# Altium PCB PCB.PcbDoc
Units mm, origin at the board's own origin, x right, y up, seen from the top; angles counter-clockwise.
Board outline 82.53 x 49.5 mm, 2 copper layers (Top Layer, Bottom Layer); 55 components, 40 nets, 211 pads, 119 vias.
Unrouted connection lines stored in the file: 2.
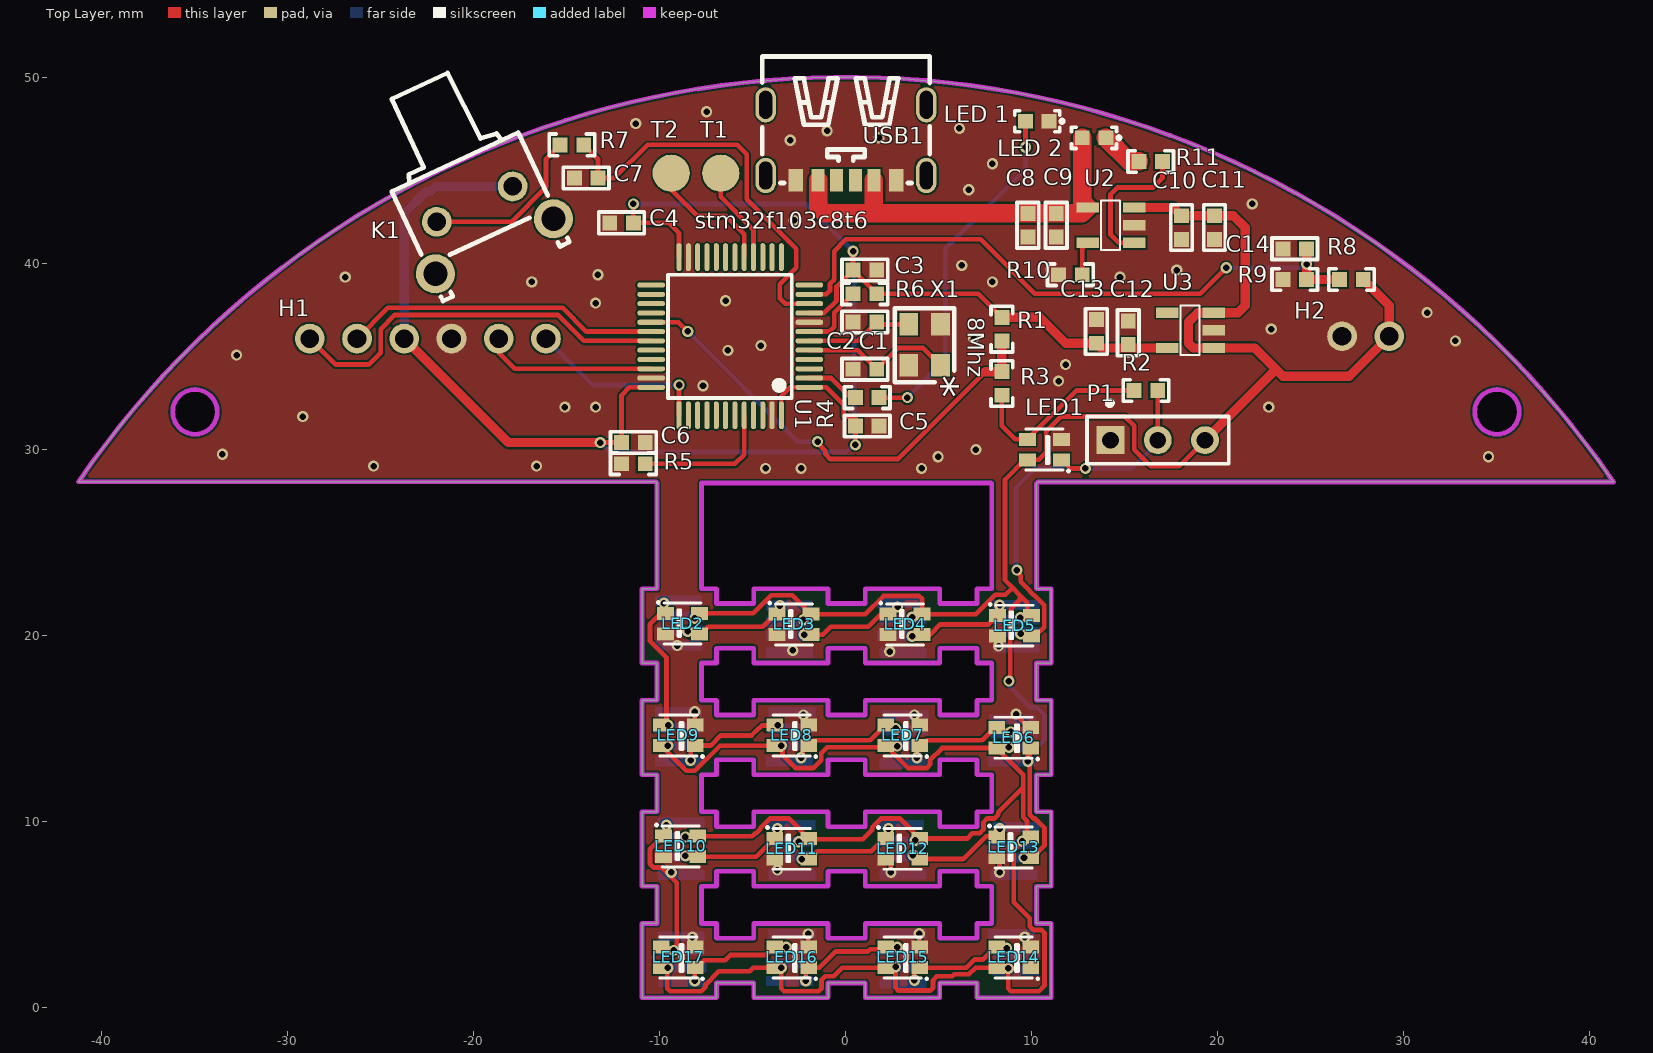
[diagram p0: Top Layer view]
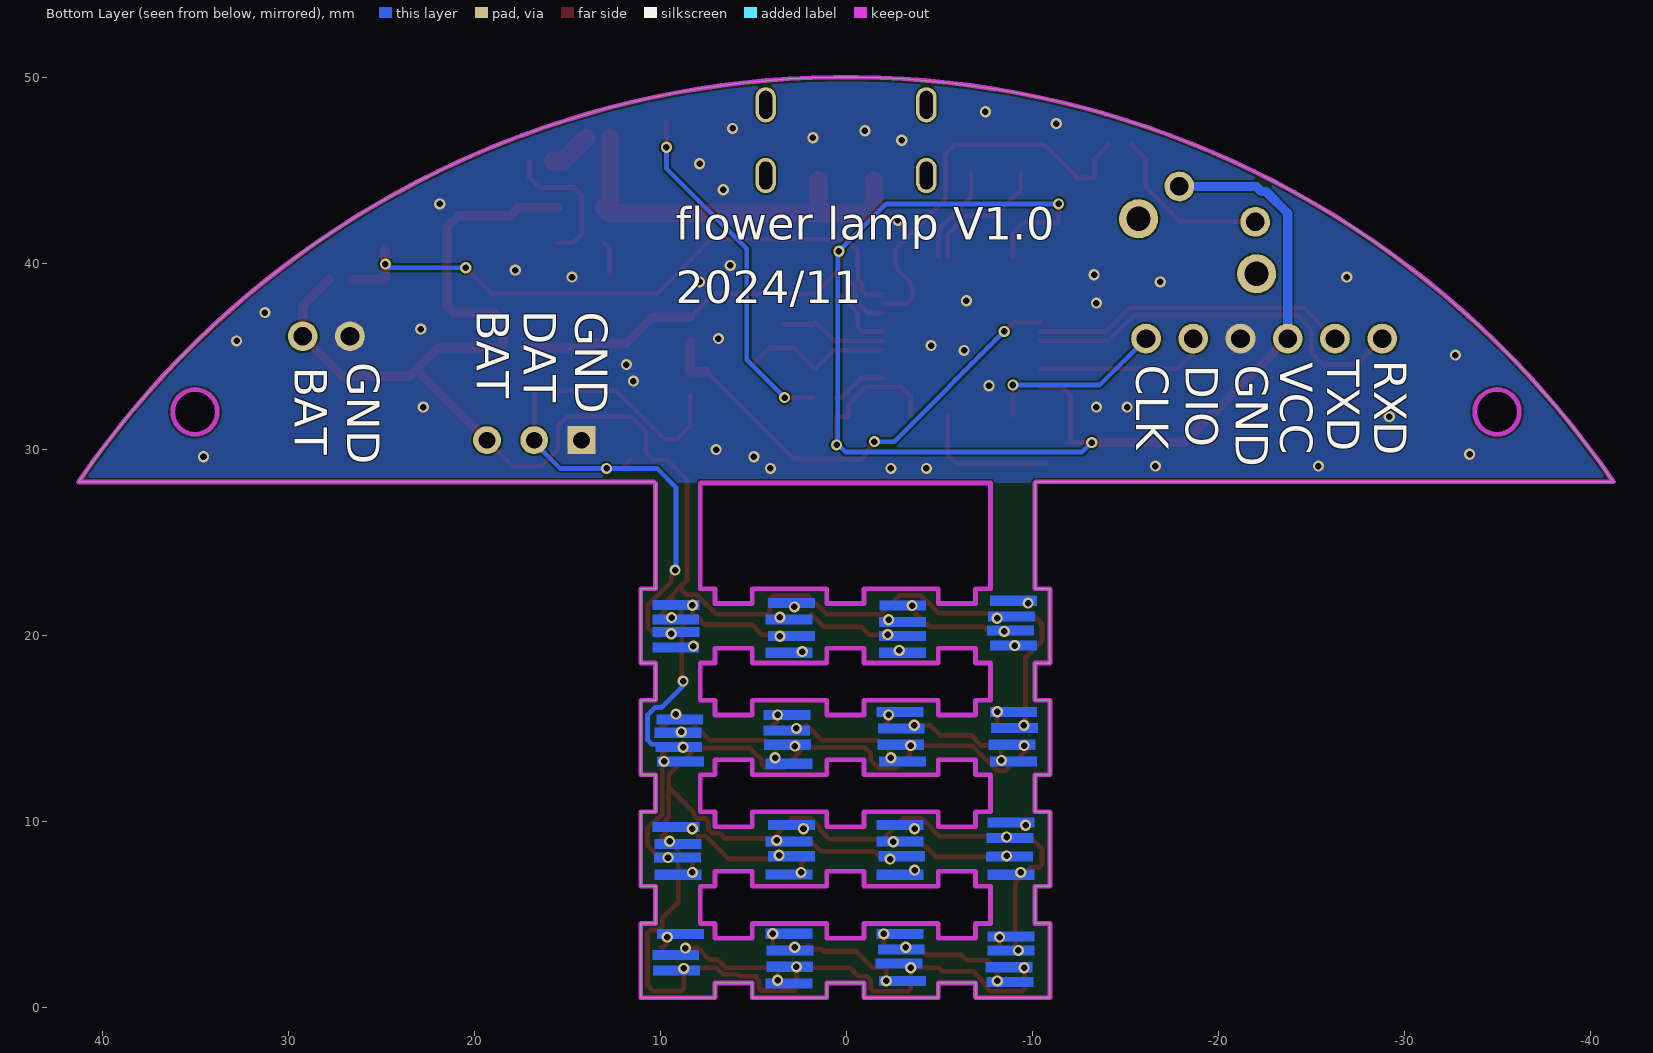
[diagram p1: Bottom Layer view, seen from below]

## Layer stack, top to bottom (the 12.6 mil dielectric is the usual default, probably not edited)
Top Solder: solder mask 0.0102, Solder Resist, Dk 3.5
Top Layer: signal copper 0.0356
Dielectric 1: dielectric 0.32, FR-4, Dk 4.8
Bottom Layer: signal copper 0.0356
Bottom Solder: solder mask 0.0102, Solder Resist, Dk 3.5

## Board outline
-10.962,0.497 -10.962,4.497 -10.162,4.497 -10.162,6.497 -10.962,6.497 -10.962,10.497 -10.162,10.497 -10.162,12.497 -10.962,12.497 -10.962,16.497 -10.162,16.497 -10.162,18.497 -10.962,18.497 -10.962,22.497 -10.162,22.497 -10.162,28.192 -10.206,28.236 -41.264,28.236 cw(c0,0) 41.266,28.233 10.326,28.233 10.238,28.145 10.238,22.497 11.038,22.497 11.038,18.497 10.238,18.497 10.238,16.497 11.038,16.497 11.038,12.497 10.238,12.497 10.238,10.497 11.038,10.497 11.038,6.497 10.238,6.497 10.238,4.497 11.038,4.497 11.038,0.497 7.038,0.497 7.038,1.297 5.038,1.297 5.038,0.497 1.038,0.497 1.038,1.297 -0.962,1.297 -0.962,0.497 -4.962,0.497 -4.962,1.297 -6.962,1.297 -6.962,0.497
cut-out: 33.8,32 ccw(c35,32) 35,30.8 ccw(c35,32) 36.2,32 ccw(c35,32) 35,33.2 ccw(c35,32)
cut-out: -35,30.8 cw(c-35,32) -36.2,32 cw(c-35,32) -35,33.2 cw(c-35,32) -33.8,32 cw(c-35,32)
cut-out: -6.962,21.697 -4.962,21.697 -4.962,22.497 -0.962,22.497 -0.962,21.697 1.038,21.697 1.038,22.497 5.038,22.497 5.038,21.697 7.038,21.697 7.038,22.497 7.838,22.497 7.838,28.158 7.817,28.179 -7.762,28.179 -7.762,22.497 -6.962,22.497
cut-out: -7.762,4.497 -6.962,4.497 -6.962,3.697 -4.962,3.697 -4.962,4.497 -0.962,4.497 -0.962,3.697 1.038,3.697 1.038,4.497 5.038,4.497 5.038,3.697 7.038,3.697 7.038,4.497 7.838,4.497 7.838,6.497 7.038,6.497 7.038,7.297 5.038,7.297 5.038,6.497 1.038,6.497 1.038,7.297 -0.962,7.297 -0.962,6.497 -4.962,6.497 -4.962,7.297 -6.962,7.297 -6.962,6.497 -7.762,6.497
cut-out: -4.962,9.697 -4.962,10.497 -0.962,10.497 -0.962,9.697 1.038,9.697 1.038,10.497 5.038,10.497 5.038,9.697 7.038,9.697 7.038,10.497 7.838,10.497 7.838,12.497 7.038,12.497 7.038,13.297 5.038,13.297 5.038,12.497 1.038,12.497 1.038,13.297 -0.962,13.297 -0.962,12.497 -4.962,12.497 -4.962,13.297 -6.962,13.297 -6.962,12.497 -7.762,12.497 -7.762,10.497 -6.962,10.497 -6.962,9.697
cut-out: -7.762,16.497 -6.962,16.497 -6.962,15.697 -4.962,15.697 -4.962,16.497 -0.962,16.497 -0.962,15.697 1.038,15.697 1.038,16.497 5.038,16.497 5.038,15.697 7.038,15.697 7.038,16.497 7.838,16.497 7.838,18.497 7.038,18.497 7.038,19.297 5.038,19.297 5.038,18.497 1.038,18.497 1.038,19.297 -0.962,19.297 -0.962,18.497 -4.962,18.497 -4.962,19.297 -6.962,19.297 -6.962,18.497 -7.762,18.497

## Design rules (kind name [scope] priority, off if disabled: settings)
Clearance [All] p1: gap=0.1 ignorepadtopadclearanceinfootprint=FALSE except(0: Arc-Hole Track-Hole SMDPad-Hole THPad-Hole Via-Hole Fill-Hole Poly-Hole Region-Hole Text-Hole; 0.102: Arc-Arc Arc-Track Arc-SMDPad Arc-THPad Track-Track Track-SMDPad Track-THPad SMDPad-SMDPad SMDPad-THPad THPad-THPad; 0.127: Arc-Via Track-Via SMDPad-Via SMDPad-Text THPad-Via Via-Via; 0.254: Arc-Text Track-Text THPad-Text Via-Text Fill-Text Poly-Text Region-Text Text-Text)
DiffPairsRouting [All] p1: maxlimit=0.254 minlimit=0.15 mostfreqgap=0.254 toplayer_minwidth=0.2 toplayer_maxwidth=0.381 toplayer_prefwidth=0.25 bottomlayer_minwidth=0.2 bottomlayer_maxwidth=0.381 bottomlayer_prefwidth=0.25 maxuncoupledlength=12.7
HoleSize [All] p1: absolutevalues=TRUE maxlimit=30 minlimit=0.025 maxpercent=80.000 minpercent=20.000
HoleToHoleClearance [All] p1: gap=0.152 allowstackedmicrovias=TRUE
MinimumSolderMaskSliver [All] p1: minsoldermaskwidth=0
PlaneClearance [All] p1: clearance=0.254
PlaneConnect [All] p1: planeconnectstyle=Direct reliefexpansion=0.508 reliefentries=4 reliefconductorwidth=0.254 reliefairgap=0.254
PolygonConnect [All] p1: connectstyle=Direct reliefconductorwidth=0.254 reliefentries=4 polygonreliefangle="90 Angle" airgapwidth=0.254
RoutingVias [All] p1: holewidth=0.711 width=1.27 viastyle="Through Hole" minholewidth=0.3 minwidth=0.5 maxholewidth=30 maxwidth=30
SilkToSilkClearance [All] p1: silktosilkclearance=0
SilkToSolderMaskClearance [IsPad] p1: minsilkscreentomaskgap=0 clearancetoexposedcopper=TRUE
SolderMaskExpansion [All] p1: expansion=0.102 istentingtop=FALSE
Width [All] p1: maxlimit=3 minlimit=0.1 preferedwidth=0.254
22 further rules are at their usual default settings.

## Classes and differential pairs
component class Sheet1: C1 C2 C3 C4 C5 C6 C7 C8 C9 C10 C11 C12 C13 C14 H1 H2 K1 LED1 LED2 LED3 LED4 LED5 LED6 LED7 LED8 LED9 LED10 LED11 LED12 LED13 LED14 LED15 LED16 LED17 "LED 1" "LED 2" P1 R1 R3 R5 R7 R9 R11 T1 T2 U1 U2 U3 USB1 X1

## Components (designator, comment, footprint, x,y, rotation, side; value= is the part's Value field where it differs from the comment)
C1 "12pF" CC1608-0603 1.016,34.29 r0 top
C2 "12pF" CC1608-0603 1.016,36.83 r0 top
C3 "100NF" CC1608-0603 1.016,39.624 r180 top
C4 "100NF" CC1608-0603 -12.065,42.164 r0 top
C5 "100NF" CC1608-0603 1.143,31.242 r180 top
C6 "100NF" CC1608-0603 -11.43,30.353 r180 top
C7 "12pF" CC1608-0603 -13.97,44.577 r0 top
C8 "1UF" CC1608-0603 9.779,42.037 r90 top
C9 "100NF" CC1608-0603 11.303,42.037 r90 top
C10 "1UF" CC1608-0603 18.034,41.91 r90 top
C11 "100NF" CC1608-0603 19.812,41.91 r90 top
C12 "1UF" CC1608-0603 15.179,36.25 r270 top
C13 "100NF" CC1608-0603 13.462,36.322 r270 top
C14 "100PF" CC1608-0603 24.13,40.767 r0 top
H1 "Header_6P_Curved" Header_2_54_6PW -28.829,35.941 r0 top
H2 "Header_2P_Curved" Header_2_54_2PW 26.67,36.068 r0 top
K1 "SW-TH_4P_H" SW-TH_KH-6X6X7H-ZJ -19.431,42.037 r25 top locked
LED1 "WS2812B-2020" WS2812B-2020 10.668,29.972 r180 top
LED2 "WS2812B-2020" WS2812B-2020 -8.789,20.616 r0 top
LED3 "WS2812B-2020" WS2812B-2020 -2.794,20.574 r0 top
LED4 "WS2812B-2020" WS2812B-2020 3.175,20.574 r0 top
LED5 "WS2812B-2020" WS2812B-2020 9.061,20.507 r0 top
LED6 "WS2812B-2020" WS2812B-2020 9.017,14.478 r180 top
LED7 "WS2812B-2020" WS2812B-2020 3.048,14.605 r180 top
LED8 "WS2812B-2020" WS2812B-2020 -2.921,14.605 r180 top
LED9 "WS2812B-2020" WS2812B-2020 -9.017,14.605 r180 top
LED10 "WS2812B-2020" WS2812B-2020 -8.89,8.636 r0 top
LED11 "WS2812B-2020" WS2812B-2020 -2.921,8.509 r0 top
LED12 "WS2812B-2020" WS2812B-2020 3.048,8.509 r0 top
LED13 "WS2812B-2020" WS2812B-2020 9.017,8.585 r0 top
LED14 "WS2812B-2020" WS2812B-2020 9.017,2.667 r180 top
LED15 "WS2812B-2020" WS2812B-2020 3.048,2.667 r180 top
LED16 "WS2812B-2020" WS2812B-2020 -2.921,2.667 r180 top
LED17 "WS2812B-2020" WS2812B-2020 -9.017,2.667 r180 top
"LED 1" "LED 0603" "LED 0603" 10.287,47.625 r0 top
"LED 2" "LED 0603" "LED 0603" 13.335,46.736 r0 top
P1 "Header 3" HDR1X3 14.224,30.48 r0 top
R1 "10K" CR1608-0603 8.382,36.449 r270 top
R2 "0R" CR1608-0603 16.129,33.147 r0 top
R3 "0R" CR1608-0603 8.382,33.528 r270 top
R4 "1K" CR1608-0603 1.143,32.766 r180 top
R5 "10K" CR1608-0603 -11.43,29.21 r0 top
R6 "10K" CR1608-0603 1.016,38.354 r180 top
R7 "1K" CR1608-0603 -14.732,46.355 r180 top
R8 "10K" CR1608-0603 27.178,39.116 r0 top
R9 "10K" CR1608-0603 24.13,39.116 r0 top
R10 "2K" CR1608-0603 12.065,39.37 r0 top
R11 "2K" CR1608-0603 16.383,45.466 r180 top
T1 "test" test -6.731,44.831 r0 top
T2 "test" test -9.398,44.831 r0 top
U1 "STM32F103C8T6" LQFP-48 -6.223,36.068 r90 top locked
U2 "TP4054" SOT23-5 15.494,42.992 r270 top
U3 "RT9013-33GB" SOT23-5 19.772,37.338 r270 top
USB1 "TYPE_C_SMD_6P" TYPE-C-SMD_TYPE-C-6P 0,46.482 r180 top locked
X1 "3225_8M" XTAL-3225 3.38,34.503 r90 top

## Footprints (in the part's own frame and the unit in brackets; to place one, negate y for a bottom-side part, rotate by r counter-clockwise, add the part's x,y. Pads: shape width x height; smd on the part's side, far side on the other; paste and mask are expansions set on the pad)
CC1608-0603 [mm]
  rect 0.8x0.8 smd: 1(-0.635,0) 2(0.635,0)
  silkscreen extent -1.23,-0.58 1.23,0.58, body extent -0.8,-0.4 0.8,0.4, height 0.3
CR1608-0603 [mm]
  rect 0.8x0.8 smd: 1(-0.635,0) 2(0.635,0)
  silkscreen extent -1.23,-0.58 1.23,0.58, body extent -0.8,-0.4 0.8,0.4, height 0.45
HDR1X3 [mm] "Connector; Header; 3 Position"
  rect 1.5x1.5 hole 0.9: 1(0,0)
  round 1.5 hole 0.9: 2(2.54,0) 3(5.08,0)
  silkscreen extent -1.27,-1.27 6.35,2.14, body extent -1.27,-1.27 6.35,1.27, height 8.54
Header_2_54_2PW [mm] "弯的排针"
  round 1.6 hole 1: 1(0,0) 2(2.54,0)
  body extent -2.52,-7.47 5.18,0.38, height 5.8
Header_2_54_6PW [mm] "6P弯针"
  round 1.6 hole 1: 1(0,0) 2(2.54,0) 3(5.08,0) 4(7.62,0) 5(10.16,0) 6(12.7,0)
  body extent -2.56,-7.48 15.3,0.37, height 5.8
"LED 0603" [mm]
  rect 0.8x0.8 smd: 1(-0.635,0) 2(0.635,0)
  silkscreen extent -1.21,-0.57 1.4,0.57, body extent -0.8,-0.4 0.8,0.4, height 0.6
LQFP-48 [mm]
  oval 0.27x1.5 smd: 1(-2.75,-4.25) 2(-2.25,-4.25) 3(-1.75,-4.25) 4(-1.25,-4.25) 5(-0.75,-4.25) 6(-0.25,-4.25) 7(0.25,-4.25) 8(0.75,-4.25) 9(1.25,-4.25) 10(1.75,-4.25) 11(2.25,-4.25) 12(2.75,-4.25) 25(2.75,4.25) 26(2.25,4.25) 27(1.75,4.25) 28(1.25,4.25) 29(0.75,4.25) 30(0.25,4.25) 31(-0.25,4.25) 32(-0.75,4.25) 33(-1.25,4.25) 34(-1.75,4.25) 35(-2.25,4.25) 36(-2.75,4.25)
  oval 1.5x0.27 smd: 13(4.25,-2.75) 14(4.25,-2.25) 15(4.25,-1.75) 16(4.25,-1.25) 17(4.25,-0.75) 18(4.25,-0.25) 19(4.25,0.25) 20(4.25,0.75) 21(4.25,1.25) 22(4.25,1.75) 23(4.25,2.25) 24(4.25,2.75) 37(-4.25,2.75) 38(-4.25,2.25) 39(-4.25,1.75) 40(-4.25,1.25) 41(-4.25,0.75) 42(-4.25,0.25) 43(-4.25,-0.25) 44(-4.25,-0.75) 45(-4.25,-1.25) 46(-4.25,-1.75) 47(-4.25,-2.25) 48(-4.25,-2.75)
  silkscreen extent -3.33,-3.31 3.3,3.34, body extent -4.47,-4.54 4.53,4.46, height 1.56
SOT23-5 [mm] "适用于MIC5205"
  rect 0.55x1.2 smd: 1(1.905,0) 2(0.955,0) 3(0.005,0) 4(0.005,-2.5) 5(1.905,-2.5)
  silkscreen extent -0.38,-1.78 2.29,-0.76, body extent -0.6,-2.82 2.5,0.38, height 1.45
SW-TH_KH-6X6X7H-ZJ [mm]
  round 1.6 hole 1 paste+0 mask+0.05: 1(2.25,1.25) 2(-2.25,1.25)
  round 2.1 hole 1.3 paste+0 mask+0.05: 3(3.5,-1.25) 4(-3.5,-1.25)
  silkscreen extent -3.75,-2.75 3.75,8.25, body extent -3.75,-2.48 3.75,5.67, height 7.5
test [mm]
  round 2 smd: 0(0,0)
TYPE-C-SMD_TYPE-C-6P [mm]
  oval 1.1x1.9 hole 0.7 slot 1.5 at 90 deg paste+0 mask+0.051: 7(-4.32,-2.025) 7(-4.32,1.775) 7(4.32,-2.025) 7(4.32,1.775)
  rect 0.7x1.2 smd paste-100 mask+0.051: A5(-0.5,2.025) A9(1.5,2.025) B5(0.5,2.025) B9(-1.5,2.025)
  rect 0.8x1.2 smd paste-100 mask+0.051: A12(2.7,2.025) B12(-2.7,2.025)
  silkscreen extent -4.5,-4.63 4.5,2.18, body extent -4.44,-4.47 4.49,2.43, height 3.18
WS2812B-2020 [mm]
  rect 0.9x0.7 smd paste+0 mask+0.051: 1(-0.915,0.55) 2(-0.915,-0.55) 3(0.915,-0.55) 4(0.915,0.55)
  silkscreen extent -1.3,-1.1 1,1.15, body extent -1.1,-1 1.1,1, height 0.84
XTAL-3225 [mm]
  rect 1.2x1 smd: 1(0,-1.7) 2(2.2,-1.7) 3(2.2,0) 4(0,0)
  silkscreen extent -0.91,-2.44 3.07,0.76, body extent -0.43,-2.15 2.77,0.35, height 0.61

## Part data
C1 C2 C3 C4 C5 C6 C7 C8 C9 C10 C11 C12 C13 C14: library part "Cap Chip 0603", "0603封装的电容"
H1: "弯的6P排针"
H2: "弯的2P排针"
K1: "卧式轻触开关"
LED1 LED2 LED3 LED4 LED5 LED6 LED7 LED8 LED9 LED10 LED11 LED12 LED13 LED14 LED15 LED16 LED17: JLCPCB Part Class="Extended Part", Manufacturer=worldsemi
P1: "Header, 3-Pin"
R1 R2 R3 R4 R5 R6 R7 R8 R9 R10 R11: library part "Resistor Chip 0603", "0603封装电阻"
T1 T2: "测试点"
U1: JLCPCB Part Class="Basic Part", Manufacturer=ST(意法半导体)
U2: "迷你充电IC SOT-23-5"
U3: "LDO 2.2-5.2V IN 500Ma OUT SOT23-5"
USB1: JLCPCB Part Class="Extended Part", Manufacturer=null
X1: library part "XTAL 3225", "3225封装的晶振"

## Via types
v1: diameter 0.6, hole 0.35, Top Layer to Bottom Layer, tented both sides, 119 vias

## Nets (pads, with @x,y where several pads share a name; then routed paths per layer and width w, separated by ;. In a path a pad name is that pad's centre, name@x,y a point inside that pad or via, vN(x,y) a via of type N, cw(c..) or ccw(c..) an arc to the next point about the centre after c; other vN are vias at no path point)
5V: "LED 2.1" C8.2 C9.2 U2.4 USB1.A9 USB1.B9 | length 22
  Top Layer w1: USB1.A9 -1.5,43.029 -1.143,42.672 1.778,42.672 ; USB1.B9 1.5,42.95 1.778,42.672 ; 12.7,46.736 12.7,43.281 U2.4 12.679,42.672 C9.2 C8.2 1.778,42.672
ADCIN1: C14.2 R8.1 R9.2 U1.11 | length 34.4
  Top Layer w0.254: U1.11 -1.052,38.318 -0.864,38.506 -0.864,38.882 -0.635,39.111 -0.635,40.64 0,41.275 7.239,41.275 10.16,38.354 19.05,38.354 v1(20.447,39.751)
  Top Layer w0.5: C14.2 v1(24.765,39.941) R9.2 R8.1
  Bottom Layer w0.254: v1(20.447,39.751) 24.575,39.751 v1(24.765,39.941)
BAT: C10.2 C11.2 H2.2 LED1.4 LED2.4 LED3.4 LED4.4 LED5.4 LED6.4 LED7.4 LED8.4 LED9.4 LED10.4 LED11.4 LED12.4 LED13.4 LED14.4 LED15.4 LED16.4 LED17.4 P1.3 R8.2 U2.3 U3.1 U3.3 | length 178.7
  Top Layer w0.254: LED17.4 -9.832,2.117 -9.609,1.894 -9.609,1.001 -9.46,0.853 -7.783,0.853 -7.55,1.086 -7.55,1.211 -6.831,1.93 -5.176,1.93 -4.99,2.117 LED16.4 v1(-3.481,2.117) -3.481,1.001 -3.332,0.853 -1.466,0.853 -1.318,1.001 -1.318,1.444 -1.109,1.653 -0.666,1.653 -0.202,2.117 LED15.4 2.154,2.138 2.646,2.138 v1(2.667,2.159) 2.667,1.038 2.816,0.889 4.534,0.889 4.682,1.038 4.682,1.444 4.891,1.653 5.717,1.653 5.825,1.761 6.611,1.761 6.967,2.117 LED14.4 8.202,2.117 8.223,2.096 v1@8.699,2.096 ; LED9.4 -8.577,12.7 -8.128,12.7 -6.773,14.055 LED8.4 v1(-3.481,14.055) -3.415,13.989 -3.415,13.575 -2.693,12.853 -1.752,12.853 -1.327,13.278 -1.327,13.659 -1.016,13.97 2.048,13.97 LED7.4 ; LED10.4 -5.038,9.186 -4.883,9.341 -4.815,9.341 -4.606,9.55 -4.606,9.618 -4.083,10.141 -3.088,10.141 -1.964,9.017 0.905,9.017 1.331,9.443 1.394,9.505 cw(c1.739,9.505) 1.494,9.749 1.886,10.141 2.881,10.141 LED12.4 ; LED2.4 -4.99,21.166 -4.015,22.141 -2.896,22.141 LED3.4 1.043,21.124 2.017,22.098 3.941,22.098 4.09,21.949 LED4.4 6.989,21.124 8.026,22.161 8.572,22.161 8.954,22.543 ; v1(2.743,14.03) 2.731,14.042 2.245,14.042 2.456,13.832 2.456,13.732 3.335,12.853 4.344,12.853 4.513,13.022 4.513,13.275 5.166,13.928 LED6.4 ; v1(3.728,8.964) 3.868,8.964 LED12.4 ; v1(8.721,2.074) 8.721,1.001 8.869,0.853 10.378,0.853 10.668,1.143 10.668,3.993 10.519,4.141 10.091,4.141 9.882,4.35 9.882,4.778 9.017,5.644 9.017,8.414 9.482,8.879 v1(9.482,8.912) ; v1(8.763,13.97) 8.624,13.97 8.603,13.949 8.123,13.949 LED6.4 ; v1(8.763,17.526) 8.825,17.588 8.825,20.402 8.782,20.444 8.782,20.57 8.871,20.658 8.871,21.417 9.353,21.899 9.353,22.143 ; v1(9.379,20.936) 9.439,20.997 9.682,20.997 LED5.4@9.859,21.174 ; LED13.4@9.705,9.135 LED13.4@9.609,9.039 ; LED13.4@9.805,9.135 LED13.4 9.736,9.331 9.736,9.993 9.527,10.202 9.527,11.813 ; LED5.4 LED5.4@9.859,21.174 ; P1.3 17.907,29.083 16.383,29.083 15.494,29.972 15.494,31.242 14.986,31.75 11.557,31.75 10.768,30.961 10.768,29.818 10.372,29.422 LED1.4 9.61,29.422 8.549,28.361 8.549,22.947 8.954,22.543 ; LED12.4 6.519,9.059 6.801,9.341 7.185,9.341 7.394,9.55 7.394,9.934 7.601,10.141 7.985,10.141 8.194,10.35 8.194,10.48 9.527,11.813 ; LED6.4 9.527,12.503 9.527,11.813 ; 8.954,22.543 9.353,22.143 ; 9.353,22.143 9.753,21.743 9.753,21.28 LED5.4@9.859,21.174 ; v1(9.482,8.912) 9.609,8.912 LED13.4@9.609,9.039 ; v1(9.482,8.912) LED13.4@9.609,9.039
  Top Layer w0.5: U2.3 17.592,42.987 C10.2 C11.2 20.828,42.545 21.463,41.91 21.463,37.719 21.077,37.333 U3.3 18.918,37.333 18.415,36.83 18.415,35.687 18.669,35.433 U3.1 21.971,35.433 23.05,34.353 ; P1.3 23.05,34.227 23.05,34.353 ; R8.2 29.21,37.719 H2.2 27.051,33.909 23.495,33.909 23.05,34.353
  Bottom Layer w0.254: -8.898,20.995 -8.206,20.995 v1(-8.119,20.907) ; v1(2.743,14.03) 3.073,14.03 3.149,14.105 ; 3.199,8.959 3.204,8.964 v1(3.728,8.964) ; v1(8.763,17.526) 8.763,17.272 9.933,16.102 10.284,16.102 10.668,15.718 10.668,14.351 10.445,14.128 9.567,14.128 ; v1@9.136,20.907 9.35,20.907 v1(9.379,20.936)
  other v1: -9.577,2.117 -2.54,8.89 -8.636,9.144 -9.577,14.055 -2.286,20.828 3.556,20.955
BOOT0: R5.2 U1.44 | length 7.6
  Top Layer w0.254: R5.2 -5.969,29.21 -5.473,29.706 U1.44
DO: LED1.1 LED5.3 P1.2 R2.2 | length 22.1
  Top Layer w0.254: v1(9.191,23.495) 9.191,23.401 9.398,23.194 9.398,22.872 9.882,22.388 9.882,22.35 10.091,22.141 10.129,22.141 10.655,21.615 10.655,20.434 10.178,19.957 LED5.3 ; LED1.1 12.049,28.956 v1@12.827,28.956 ; P1.2 R2.2
  Bottom Layer w0.254: v1@9.144,23.495 9.144,27.94 10.16,28.956 v1(12.874,28.956) 15.367,28.956 16.764,30.353 P1.2 ; v1@9.259,20.223 9.398,20.085 v1(9.398,20.075)
GND: "LED 1.2" C1.1 C2.1 C3.1 C4.1 C5.1 C6.1 C7.1 C8.1 C9.1 C10.1 C11.1 C12.1 C13.1 C14.1 H1.4 H2.1 LED1.2 LED2.2 LED3.2 LED4.2 LED5.2 LED6.2 LED7.2 LED8.2 LED9.2 LED10.2 LED11.2 LED12.2 LED13.2 LED14.2 LED15.2 LED16.2 LED17.2 P1.1 R5.1 R9.1 R10.1 U1.8 U1.23 U1.35 U1.47 U2.2 U3.2 USB1.A12 USB1.B12 X1.2 X1.4 | length 7.8
  Top Layer w0.254: v1(-8.255,3.767) -8.255,3.37 LED17.2 ; v1(-8.128,15.875) -8.128,15.181 LED9.2 ; v1(-2.286,15.705) -2.286,15.378 -2.063,15.155 LED8.2 ; v1(-2.032,3.937) -2.032,3.243 LED16.2 ; LED12.2 2.19,7.959 2.413,7.736 v1(2.413,7.239) ; v1(3.683,15.705) 3.683,15.378 3.906,15.155 LED7.2 ; v1(3.937,3.943) 3.937,3.243 LED15.2 ; LED13.2 8.255,7.882 v1(8.255,7.239) ; v1(9.144,15.748) 9.144,15.716 9.832,15.028 LED6.2 ; v1(9.609,3.767) 9.609,3.44 9.832,3.217 LED14.2
  other v1: -3.683,7.366 2.35,19.114 -2.862,19.177 8.209,19.407 -9.069,19.431 -4.318,28.956 -2.413,28.956 4.064,28.956 -25.4,29.083 -16.637,29.083 4.953,29.591 34.544,29.591 -33.528,29.718 6.985,29.972 -29.21,31.75 -15.113,32.258 -13.462,32.258 22.733,32.258 -7.687,33.409 11.43,33.655 11.811,34.544 -32.766,35.052 -6.35,35.306 -4.572,35.56 32.766,35.814 6.858,35.941 22.86,36.449 31.242,37.338 -13.462,37.846 -6.477,37.973 -16.891,38.989 7.874,38.989 -26.924,39.243 14.732,39.243 -13.335,39.37 17.78,39.624 6.223,39.878 -2.794,42.291 21.844,43.18 6.604,43.942 7.874,45.339 -3,46.607 1.778,46.736 -1.016,47.117 6.096,47.244 -11.303,47.498 -7.493,48.133
LED0: R4.2 U1.2 | length 2.9
  Top Layer w0.254: U1.2 -0.798,33.818 0.254,32.766 R4.2
NetK1_2: K1.2 R7.2 | length 9.2
  Top Layer w0.254: K1.2 -17.979,42.219 -16.129,44.069 -16.129,45.593 R7.2
NetLED2_1: LED2.1 LED9.3 | length 7.7
  Top Layer w0.254: LED9.3 v1(-9.567,15.155) ; LED2.1 -9.949,21.166 -10.541,20.574 -10.541,19.685 -9.652,18.796 LED9.3@-9.652,15.24
  Bottom Layer w0.254: v1(-9.567,15.155) -9.417,15.005 -9.061,15.005
  other v1: -9.789,21.716
NetLED2_3: LED2.3 LED3.1 | length 4.6
  Top Layer w0.254: LED2.3 -7.774,20.066 -7.393,20.447 -4.486,20.447 -3.809,21.124 LED3.1
  other v1: -8.509,20.193 -3.556,21.587
NetLED3_3: LED3.3 LED4.1 | length 4.5
  Top Layer w0.254: LED3.3 -1.241,20.024 -0.818,20.447 1.202,20.447 LED4.1@1.879,21.124
  Bottom Layer w0.254: v1(2.778,21.516) 2.778,21.559 v1@2.936,21.717
  other v1: -2.244,20.024
NetLED4_3: LED4.3 LED5.1 | length 6.5
  Top Layer w0.254: LED4.3@3.709,20.024 4.53,20.024 5.08,20.574 7.663,20.574 7.823,20.734 7.823,20.834 8.046,21.057 LED5.1 8.255,21.166 v1(8.255,21.607)
  Bottom Layer w0.254: v1(8.255,21.607) 9.161,21.607 9.207,21.653
  other v1: 3.556,19.939
NetLED6_1: LED6.1 LED13.3 | length 7.3
  Top Layer w0.254: v1(9.571,8.035) LED13.3@9.807,8.035 ; v1(9.779,13.208) 9.779,13.361 9.779,13.775 LED6.1 ; v1@9.882,13.208 9.882,10.35 10.125,10.107 ; v1@9.882,13.361 LED6.1@9.882,13.775 ; LED13.3 10.032,8.035 10.668,8.671 10.668,9.633 10.16,10.141
NetLED6_3: LED6.3 LED7.1 | length 6.5
  Top Layer w0.254: v1(3.81,13.407) 3.81,13.832 3.835,13.857 3.865,13.857 4.359,14.351 7.325,14.351 8.002,15.028 8.192,15.028 8.361,14.859 8.791,14.859 v1(8.857,14.793) ; LED7.1@3.81,13.902 LED7.1
  Bottom Layer w0.254: v1(8.857,14.793) 8.901,14.749 v1@9.028,14.749
NetLED7_3: LED7.3 LED8.1 | length 6.1
  Top Layer w0.254: v1(-2.413,13.407) -2.413,13.5 -2.329,13.584 -2.329,13.832 -2.106,14.055 LED8.1 -1.71,14.351 1.306,14.351 2.11,15.155 LED7.3 2.236,15.052 2.601,15.052 v1(2.667,14.986)
NetLED8_3: LED8.3 LED9.1 | length 5.6
  Top Layer w0.254: v1(-8.353,13.259) -8.353,13.832 -8.13,14.055 LED9.1 -8.097,14.06 -7.271,14.06 -6.726,14.605 -5.08,14.605 -4.699,14.986 -4.667,14.986 -4.518,15.135 -3.856,15.135 LED8.3
  other v1: -3.671,15.155
NetLED10_1: LED10.1 LED17.3 | length 8.1
  Top Layer w0.254: LED17.3 -9.829,3.114 -9.337,3.114 v1(-9.271,3.048) -9.271,3.142 -9.101,3.312 -9.101,6.688 -9.92,7.507 -10.35,7.507 -10.541,7.699 -10.541,8.473 -9.828,9.186 LED10.1
  other v1: -9.398,7.239 -9.652,9.779
NetLED10_3: LED10.3 LED11.1 | length 4.5
  Top Layer w0.254: LED10.3 -4.832,8.086 -3.859,9.059 LED11.1
  other v1: -8.636,8.128 -3.683,9.587
NetLED11_3: LED11.3 LED12.1 | length 4.6
  Top Layer w0.254: LED11.3 -1.906,7.959 -1.683,8.182 -1.683,8.233 -1.534,8.382 1.356,8.382 2.033,9.059 LED12.1
  other v1: -2.371,7.959 2.286,9.587
NetLED12_3: LED12.3 LED13.1 | length 4.5
  Top Layer w0.254: LED12.3 6.306,7.959 7.533,9.186 LED13.1@7.975,9.186
  other v1: 3.598,8.159 8.263,9.588
NetLED14_3: LED14.3 LED15.1 | length 6
  Top Layer w0.254: v1(3.675,1.443) 3.675,1.929 3.863,2.117 6.464,2.117 6.902,2.555 7.341,2.555 8.002,3.217 LED14.3 8.123,3.196 8.615,3.196 v1(8.636,3.175)
NetLED15_3: LED15.3 LED16.1 | length 6.2
  Top Layer w0.254: v1(-2.159,1.407) -2.159,2.021 -2.063,2.117 -1.439,2.117 -0.57,2.986 1.175,2.986 1.302,3.113 1.81,3.113 LED15.3@2.014,3.317 ; LED15.3 2.032,3.318 2.137,3.213 2.139,3.215 2.754,3.215 v1(2.756,3.213)
NetLED16_3: LED16.3 LED17.1 | length 6.1
  Top Layer w0.254: v1(-8.128,1.407) LED17.1@-8.128,2.091 ; LED17.1 LED17.1@-8.128,2.091 ; v1(-3.214,3.214) v1(-3.214,3.214) -3.835,3.216 LED16.3 -3.936,3.217 -4.159,2.994 -4.159,2.943 -4.308,2.794 -6.223,2.794 -6.5,2.517 -7.63,2.517 -7.779,2.369 -7.779,2.34 -8.028,2.091 LED17.1@-8.128,2.091
"NetLED 1_1": "LED 1.1" R4.1 | length 19
  Top Layer w0.254: R4.1 v1(3.302,32.766) ; v1(9.652,46.228) 9.652,47.625
  Bottom Layer w0.254: v1(3.302,32.766) 5.334,34.798 5.334,40.767 9.652,45.085 v1(9.652,46.228)
"NetLED 2_2": "LED 2.2" R11.2 | length 2.3
  Top Layer w1: 13.97,46.736 15.24,45.466 R11.2
NetR10_2: R10.2 U2.5 | length 1.8
  Top Layer w0.254: R10.2 12.7,40.793 U2.5
NetR11_1: R11.1 U2.1 | length 7.7
  Top Layer w0.254: U2.1 14.666,41.087 14.224,41.529 14.224,43.688 14.605,44.069 16.51,44.069 17.018,44.577 R11.1
NetT1_0: T1.0 U1.16 | length 5.2
  Top Layer w0.254: T1.0 -6.731,43.561 -4.973,41.803 U1.16
NetT2_0: T2.0 U1.17 | length 7
  Top Layer w0.254: T2.0 -9.398,43.942 -8.001,42.545 -6.477,42.545 -5.473,41.541 U1.17
NRST: R6.2 U1.7 | length 3.6
  Top Layer w0.254: U1.7 -0.893,36.318 -0.635,36.576 -0.635,37.338 R6.2
RCC_IN: C1.2 U1.5 X1.1 | length 8.3
  Top Layer w0.254: U1.5 0.623,35.318 C1.2 2.794,35.433 4.15,35.433 X1.1
RCC_OUT: C2.2 U1.6 X1.3 | length 5.8
  Top Layer w0.254: U1.6 0.639,35.818 C2.2 1.778,36.703 X1.3
RXD: H1.1 U1.31 | length 21.4
  Top Layer w0.254: H1.1 -27.432,34.544 -25.654,34.544 -25.019,35.179 -25.019,36.449 -24.257,37.211 -15.489,37.211 -14.096,35.818 U1.31
SWCLK: H1.6 U1.37 | length 9.8
  Top Layer w0.254: U1.37 v1(-8.973,33.445)
  Bottom Layer w0.254: H1.6 -13.633,33.445 v1(-8.973,33.445)
SWDIO: H1.5 U1.34 | length 9.3
  Top Layer w0.254: H1.5 -18.669,35.179 -17.808,34.318 U1.34
SYS_WKUP0: C7.2 R7.1 U1.10 | length 22
  Top Layer w0.254: R7.1 -13.335,45.593 C7.2 -12.446,44.577 -10.668,46.355 -5.842,46.355 -5.334,45.847 -5.334,43.434 -2.667,40.767 -2.667,39.751 -3.556,38.862 -3.556,38.1 -3.274,37.818 U1.10
TIM1CH1: R1.2 R3.1 U1.29 | length 25.6
  Top Layer w0.254: U1.29 -9.005,36.818 v1(-8.509,36.322) ; v1(-1.524,30.399) -1.524,30.305 -1.099,29.88 -1.099,29.72 -0.843,29.464 2.794,29.464 7.493,34.163
  Top Layer w0.5: 7.493,34.163 R3.1 R1.2
  Bottom Layer w0.254: v1(-8.509,36.322) -2.586,30.399 v1(-1.524,30.399)
TXD: H1.2 U1.30 | length 17
  Top Layer w0.254: H1.2 -24.638,37.592 -15.24,37.592 -13.966,36.318 U1.30
VCC: C3.2 C4.2 C5.2 C6.2 C12.2 C13.2 H1.3 K1.1 R1.1 R6.1 U1.1 U1.9 U1.24 U1.36 U1.48 U3.5 | length 105
  Top Layer w0.254: v1(-13.208,30.353) C6.2 -12.065,32.893 -11.64,33.318 U1.36 ; v1(-11.43,43.18) C4.2 -9.525,42.164 -8.973,41.612 U1.24 ; U1.48 -3.473,32.849 -3.004,33.318 U1.1 -1.06,33.318 -0.121,32.379 -0.121,31.75 0.508,31.75 v1(0.508,30.226) ; U1.9 -1.163,37.318 -0.508,37.973 -0.508,38.735 C3.2 ; v1(0.381,40.64) C3.2 ; R1.1 7.112,38.354 R6.1 C3.2
  Top Layer w0.5: H1.3 -18.161,30.353 v1(-13.208,30.353) ; R1.1 10.414,37.084 11.811,35.687 C13.2 13.716,35.433 U3.5
  Bottom Layer w0.254: v1(-13.208,30.353) -12.7,29.845 0.033,29.845 0.414,30.226 v1(0.508,30.226) 0.445,30.29 0.445,40.576 -2.159,43.18 v1(-11.43,43.18)
  Bottom Layer w0.5: H1.3 -23.749,42.672 -22.574,43.847 -22.322,43.847 -22.048,44.121 K1.1
WS2812: LED1.3 R2.1 R3.2 | length 10.1
  Top Layer w0.254: R3.2 8.382,31.242 9.102,30.522 LED1.3 12.378,33.147 R2.1
pads on no net: K1.3 K1.4 LED14.1 U1.3 U1.4 U1.12 U1.13 U1.14 U1.15 U1.18 U1.19 U1.20 U1.21 U1.22 U1.25 U1.26 U1.27 U1.28 U1.32 U1.33 U1.38 U1.39 U1.40 U1.41 U1.42 U1.43 U1.45 U1.46 U3.4 USB1.7 USB1.A5 USB1.B5

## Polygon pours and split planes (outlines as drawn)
no net on Bottom Solder "NONET_L-01_P-001" (solid): 7.366,4.318 10.668,4.318 10.668,1.143 7.493,1.143
no net on Bottom Solder "NONET_L-01_P-001" (solid): 1.397,4.191 4.699,4.191 4.699,1.054 4.534,0.889 1.524,0.889
no net on Bottom Solder "NONET_L-01_P-001" (solid): -4.572,4.191 -1.397,4.191 -1.392,4.186 -1.392,0.927 -4.356,0.927 -4.445,1.016
no net on Bottom Solder "NONET_L-01_P-001" (solid): -10.668,4.064 -7.239,4.064 -7.239,1.016 -7.366,0.889 -10.541,0.889
no net on Bottom Solder "NONET_L-01_P-001" (solid): 7.366,10.16 10.541,10.16 10.668,10.033 10.668,6.858 7.493,6.858
no net on Bottom Solder "NONET_L-01_P-001" (solid): 1.397,10.287 4.699,10.287 4.699,6.858 4.572,6.731 1.397,6.731
no net on Bottom Solder "NONET_L-01_P-001" (solid): -4.572,10.16 -1.27,10.16 -1.27,6.731 -4.572,6.731
no net on Bottom Solder "NONET_L-01_P-001" (solid): -10.668,10.16 -7.366,10.16 -7.366,6.858 -7.493,6.731 -10.541,6.731
no net on Bottom Solder "NONET_L-01_P-001" (solid): -10.541,16.256 -7.239,16.256 -7.239,12.827 -10.541,12.827
no net on Bottom Solder "NONET_L-01_P-001" (solid): -4.572,16.256 -1.397,16.256 -1.397,12.7 -4.445,12.7
no net on Bottom Solder "NONET_L-01_P-001" (solid): 1.524,16.129 4.572,16.129 4.572,12.827 1.524,12.827
no net on Bottom Solder "NONET_L-01_P-001" (solid): 7.493,15.875 10.057,15.875 10.317,15.615 10.317,12.924 10.414,12.827 10.287,12.7 7.493,12.7
no net on Bottom Solder "NONET_L-01_P-001" (solid): 7.366,22.098 10.795,22.098 10.795,18.923 10.668,18.796 7.366,18.796
no net on Bottom Solder "NONET_L-01_P-001" (solid): 1.397,22.225 4.699,22.225 4.699,18.796 1.27,18.796
no net on Bottom Solder "NONET_L-01_P-001" (solid): -4.572,22.098 -1.27,22.098 -1.27,18.796 -4.572,18.796
no net on Bottom Solder "NONET_L-01_P-001" (solid): -10.541,22.098 -7.366,22.098 -7.366,18.923 -10.541,18.923
GND on Bottom Layer "GND_L02_P002" (solid, remove dead copper, pour order 2): -10.162,28.192 -10.206,28.236 -41.264,28.236 cw(c0,0) 41.266,28.233 10.326,28.233 10.285,28.192
GND on Top Layer "GND_L01_P003" (solid, pour order 3): -10.962,0.497 -10.962,4.497 -10.162,4.497 -10.162,6.497 -10.962,6.497 -10.962,10.497 -10.162,10.497 -10.162,12.497 -10.962,12.497 -10.962,16.497 -10.162,16.497 -10.162,18.497 -10.962,18.497 -10.962,22.497 -10.162,22.497 -10.162,28.192 -10.206,28.236 -41.264,28.236 cw(c0,0) 41.266,28.233 10.326,28.233 10.238,28.145 10.238,22.497 11.038,22.497 11.038,18.497 10.238,18.497 10.238,16.497 11.038,16.497 11.038,12.497 10.238,12.497 10.238,10.497 11.038,10.497 11.038,6.497 10.238,6.497 10.238,4.497 11.038,4.497 11.038,0.497 7.038,0.497 7.038,1.297 5.038,1.297 5.038,0.497 1.038,0.497 1.038,1.297 -0.962,1.297 -0.962,0.497 -4.962,0.497 -4.962,1.297 -6.962,1.297 -6.962,0.497

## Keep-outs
Keep-Out Layer:
  circle w0.254: c35,32 r1.2
  circle w0.254: c-35,32 r1.2
  lines w0.254: -10.206,28.236 -41.264,28.236 cw(c0,0) 41.266,28.233 10.326,28.233 ; -10.162,28.192 -10.162,22.497 -10.962,22.497 -10.962,21.697 -10.962,19.297 -10.962,18.497 -10.162,18.497 -10.162,16.497 -10.962,16.497 -10.962,15.697 -10.962,13.297 -10.962,12.497 -10.162,12.497 -10.162,10.497 -10.962,10.497 -10.962,6.497 -10.162,6.497 -10.162,4.497 -10.962,4.497 -10.962,0.497 -10.162,0.497 -7.762,0.497 -6.962,0.497 -6.962,1.297 -4.962,1.297 -4.962,0.497 -0.962,0.497 -0.962,1.297 1.038,1.297 1.038,0.497 5.038,0.497 5.038,1.297 7.038,1.297 7.038,0.497 11.038,0.497 11.038,1.297 11.038,3.697 11.038,4.497 10.238,4.497 10.238,6.497 11.038,6.497 11.038,7.297 11.038,9.697 11.038,10.497 10.238,10.497 10.238,12.497 11.038,12.497 11.038,13.297 11.038,15.697 11.038,16.497 10.238,16.497 10.238,18.497 11.038,18.497 11.038,19.297 11.038,21.697 11.038,22.497 10.238,22.497 10.238,28.145 ; 7.817,28.179 -7.762,28.179 -7.762,22.497 -6.962,22.497 -6.962,21.697 -4.962,21.697 -4.962,22.497 -0.962,22.497 -0.962,21.697 1.038,21.697 1.038,22.497 5.038,22.497 5.038,21.697 7.038,21.697 7.038,22.497 7.838,22.497 7.838,28.158 ; -7.762,4.497 -7.762,6.497 -6.962,6.497 -6.962,7.297 -4.962,7.297 -4.962,6.497 -0.962,6.497 -0.962,7.297 1.038,7.297 1.038,6.497 5.038,6.497 5.038,7.297 7.038,7.297 7.038,6.497 7.838,6.497 7.838,4.497 7.038,4.497 7.038,3.697 5.038,3.697 5.038,4.497 1.038,4.497 1.038,3.697 -0.962,3.697 -0.962,4.497 -4.962,4.497 -4.962,3.697 -6.962,3.697 -6.962,4.497 -7.762,4.497 ; -7.762,10.497 -7.762,12.497 -6.962,12.497 -6.962,13.297 -4.962,13.297 -4.962,12.497 -0.962,12.497 -0.962,13.297 1.038,13.297 1.038,12.497 5.038,12.497 5.038,13.297 7.038,13.297 7.038,12.497 7.838,12.497 7.838,10.497 7.038,10.497 7.038,9.697 5.038,9.697 5.038,10.497 1.038,10.497 1.038,9.697 -0.962,9.697 -0.962,10.497 -4.962,10.497 -4.962,9.697 -6.962,9.697 -6.962,10.497 -7.762,10.497 ; -7.762,16.497 -6.962,16.497 -6.962,15.697 -4.962,15.697 -4.962,16.497 -0.962,16.497 -0.962,15.697 1.038,15.697 1.038,16.497 5.038,16.497 5.038,15.697 7.038,15.697 7.038,16.497 7.838,16.497 7.838,18.497 7.038,18.497 7.038,19.297 5.038,19.297 5.038,18.497 1.038,18.497 1.038,19.297 -0.962,19.297 -0.962,18.497 -4.962,18.497 -4.962,19.297 -6.962,19.297 -6.962,18.497 -7.762,18.497 -7.762,16.497

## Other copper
Bottom Layer:
  rectangle net BAT: 7.859,1.696 10.377,2.238
  rectangle net NetLED14_3: 7.9,2.523 10.418,3.065
  rectangle net GND: 7.646,3.666 10.164,4.208
  rectangle net NetLED14_3: 1.804,0.999 4.322,1.541
  rectangle net BAT: 1.765,1.896 4.283,2.438
  rectangle net NetLED15_3: 1.745,2.776 4.263,3.318
  rectangle net GND: 1.804,3.672 4.322,4.214
  rectangle net NetLED15_3: -4.292,1.136 -1.774,1.678
  rectangle net BAT: -4.104,2.071 -1.586,2.613
  rectangle net NetLED16_3: -4.224,2.816 -1.706,3.358
  rectangle net GND: -4.165,3.666 -1.647,4.208
  rectangle net NetLED16_3: -10.068,1.086 -7.55,1.628
  rectangle net BAT: -10.025,1.871 -7.507,2.413
  rectangle net GND: -10.138,3.522 -7.62,4.064
  rectangle net NetLED10_1: -10.134,2.777 -7.616,3.319
  rectangle net NetLED10_1: -10.134,6.841 -7.616,7.383
  rectangle net NetLED10_3: -10.048,7.815 -7.53,8.357
  rectangle net BAT: -10.073,8.815 -7.555,9.357
  rectangle net NetLED10_1: -10.138,9.652 -7.62,10.194
  rectangle net NetLED10_3: -4.165,9.508 -1.647,10.05
  rectangle net BAT: -4.169,8.636 -1.651,9.178
  rectangle net NetLED11_3: -4.254,7.838 -1.736,8.38
  rectangle net GND: -4.165,6.841 -1.647,7.383
  rectangle net GND: 1.8,6.858 4.318,7.4
  rectangle net NetLED12_3: 1.665,7.838 4.183,8.38
  rectangle net BAT: 1.8,8.636 4.318,9.178
  rectangle net NetLED11_3: 1.673,9.525 4.191,10.067
  rectangle net GND: 7.773,6.841 10.291,7.383
  rectangle net NetLED6_1: 7.799,7.764 10.317,8.307
  rectangle net BAT: 7.773,8.492 10.291,9.034
  rectangle net NetLED12_3: 7.884,9.414 10.402,9.957
  rectangle net NetLED6_1: 7.646,12.937 10.164,13.479
  rectangle net BAT: 7.734,13.707 10.252,14.249
  rectangle net NetLED6_3: 7.769,14.478 10.287,15.02
  rectangle net GND: 7.679,15.193 10.197,15.735
  rectangle net NetLED6_3: 1.804,12.81 4.322,13.352
  rectangle net BAT: 1.89,13.834 4.408,14.376
  rectangle net NetLED7_3: 1.931,14.588 4.449,15.13
  rectangle net GND: 1.915,15.434 4.433,15.976
  rectangle net NetLED7_3: -4.292,12.937 -1.774,13.479
  rectangle net BAT: -4.204,13.834 -1.686,14.376
  rectangle net NetLED8_3: -4.224,14.714 -1.706,15.256
  rectangle net GND: -4.165,15.604 -1.647,16.146
  rectangle net NetLED8_3: -10.261,12.937 -7.743,13.479
  rectangle net BAT: -10.175,13.834 -7.657,14.376
  rectangle net NetLED2_1: -10.32,14.734 -7.802,15.276
  rectangle net GND: -10.261,15.604 -7.743,16.146
  rectangle net GND: -10.261,19.16 -7.743,19.702
  rectangle net NetLED2_3: -10.105,19.965 -7.587,20.507
  rectangle net BAT: -10.157,20.724 -7.639,21.266
  rectangle net NetLED2_1: -10.261,21.573 -7.743,22.115
  rectangle net NetLED2_3: -4.312,21.324 -1.794,21.866
  rectangle net BAT: -4.292,20.43 -1.774,20.972
  rectangle net NetLED3_3: -4.292,19.668 -1.774,20.21
  rectangle net GND: -4.292,18.779 -1.774,19.321
  rectangle net BAT: 1.8,20.574 4.318,21.116
  rectangle net NetLED4_3: 1.677,19.668 4.195,20.21
  rectangle net GND: 1.804,18.779 4.322,19.321
  rectangle net NetLED3_3: 1.677,21.446 4.195,21.988
  rectangle net GND: 7.896,19.05 10.414,19.592
  rectangle net DO: 7.874,19.886 10.392,20.428
  rectangle net BAT: 7.896,20.574 10.414,21.116
  rectangle net NetLED4_3: 7.874,21.336 10.392,21.878

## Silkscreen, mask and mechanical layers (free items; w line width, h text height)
Top Overlay:
  text "stm32f103c8t6" at -8.128,41.546 h1.52
  text "8Mhz" at 6.239,37.084 h1.52 r270
Bottom Overlay:
  text "flower lamp V1.0" at 9.144,40.665 h3
  text "DAT" at 17.907,37.465 h3 r90
  text "BAT" at 20.447,37.465 h3 r90
  text "GND" at 15.154,37.383 h3 r90
  text "2024/11" at 9.146,37.244 h3
  text "RXD" at -27.813,34.798 h3 r90
  text "TXD" at -25.273,34.798 h3 r90
  text "VCC" at -22.764,34.669 h3 r90
  text "GND" at 27.401,34.671 h3 r90
  text "GND" at -20.351,34.544 h3 r90
  text "DIO" at -17.684,34.544 h3 r90
  text "CLK" at -15.017,34.544 h3 r90
  text "BAT" at 30.226,34.417 h3 r90
Mechanical 1:
  lines w0.254: 0,28.236 0,50.038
